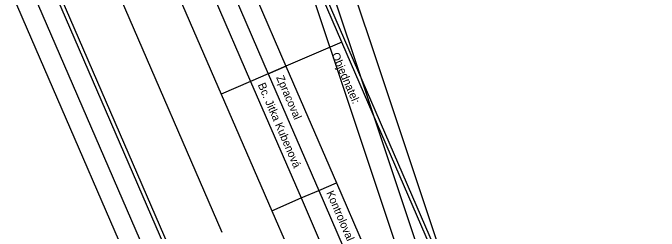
# Model space of a CAD drawing. Extents: x -866656 to -858817, y -1041816 to -1038653.
# Drawn here: x -864793.3 to -864631.9, y -1041577.1 to -1041522.5 of the extents above; entities that cross this region are included whole.
import ezdxf

# ---------------------------------------------------------------- set-up
doc = ezdxf.new("R2010")
doc.units = 0
doc.layers.add('tisk ramy', color=7, linetype='Continuous')

msp = doc.modelspace()

# ---------------------------------------------------------------- linework, layer by layer
at = {"layer": 'tisk ramy'}
for p, q in [((-864711.18, -1041529.78), (-864736.43, -1041471.4)), ((-864735.97, -1041470.24), (-864663.81, -1041637.07)), ((-864779.02, -1041489.82), (-864741.14, -1041577.38)), ((-864720.5, -1041661.59), (-864792.66, -1041494.76)), ((-864791.5, -1041495.22), (-864753.62, -1041582.78)), ((-864737.75, -1041506.62), (-864725.13, -1041535.81)), ((-864742.16, -1041508.53), (-864729.54, -1041537.72)), ((-864746.57, -1041510.43), (-864733.94, -1041539.62)), ((-864753.91, -1041513.61), (-864741.29, -1041542.8)), ((-864711.18, -1041529.78), (-864725.13, -1041535.81)), ((-864685.93, -1041588.15), (-864711.18, -1041529.78)), ((-864725.13, -1041535.81), (-864729.54, -1041537.72)), ((-864729.54, -1041537.72), (-864725.13, -1041535.81)), ((-864725.13, -1041535.81), (-864712.51, -1041565)), ((-864729.54, -1041537.72), (-864733.94, -1041539.62)), ((-864729.54, -1041537.72), (-864716.91, -1041566.9)), ((-864733.94, -1041539.62), (-864741.29, -1041542.8)), ((-864733.94, -1041539.62), (-864721.32, -1041568.81)), ((-864741.29, -1041542.8), (-864728.66, -1041571.99)), ((-864716.91, -1041566.9), (-864712.51, -1041565)), ((-864712.51, -1041565), (-864699.88, -1041594.18)), ((-864721.32, -1041568.81), (-864716.91, -1041566.9)), ((-864716.91, -1041566.9), (-864704.29, -1041596.09)), ((-864728.66, -1041571.99), (-864721.32, -1041568.81)), ((-864721.32, -1041568.81), (-864708.69, -1041597.99)), ((-864728.66, -1041571.99), (-864716.04, -1041601.17))]:
    msp.add_line(p, q, dxfattribs=at)
for points in [[(-865224.28, -1040522.07), (-864724.07, -1041678.52), (-864451.49, -1041560.62), (-864951.69, -1040404.17)], [(-864954.3, -1040410.74), (-864458.06, -1041558.01), (-864721.47, -1041671.94), (-865217.7, -1040524.67)], [(-864678.84, -1041637.08), (-863881.88, -1041371.71), (-863975.7, -1041089.93), (-864772.67, -1041355.3)], [(-863888.2, -1041368.54), (-864675.68, -1041630.76), (-864766.35, -1041358.47), (-863978.87, -1041096.25)], [(-864672.52, -1041624.44), (-864089.02, -1041430.15), (-864176.53, -1041167.33), (-864760.03, -1041361.63)]]:
    msp.add_lwpolyline(points, close=True, dxfattribs=at)

# ---------------------------------------------------------------- texts
for s, p in [('Objednatel:', (-864713.77, -1041532.9)), ('Zpracoval', (-864727.6, -1041538.62)), ('Bc. Jitka Kubenová', (-864732.2, -1041540.48)), ('Kontroloval', (-864715.09, -1041567.5))]:
    msp.add_text(s, height=2, rotation=293.3902, dxfattribs=at).set_placement(p)

doc.saveas('drawing.dxf')
